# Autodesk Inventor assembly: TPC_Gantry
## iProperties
Shininess: 64.0
Length Units: 11272
Angle Units: 11279
Time Units: 11290
Mass Units: 11286
Length Display Precision: 3
Angle Display Precision: 2
Compacted: True
Part Number: TPC_Gantry
Document SubType Name: Assembly
Created: 2004-08
Designer: Lori
Manufacturer: Standard
Standards Organization: Custom
Density: 0.0
Volumn: 0.0
Area: 0.0
PropertySet Name: Model Information
Control State: 0
Master: False
Checked Out: False
Author: Lori
